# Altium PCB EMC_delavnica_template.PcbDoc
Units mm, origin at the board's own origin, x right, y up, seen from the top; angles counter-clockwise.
Board outline 117 x 59 mm, 2 copper layers (Top Layer, Bottom Layer), stack 1.536 mm thick; 45 components, 21 nets, 110 pads, 0 vias.
Unrouted connection lines stored in the file: 68.
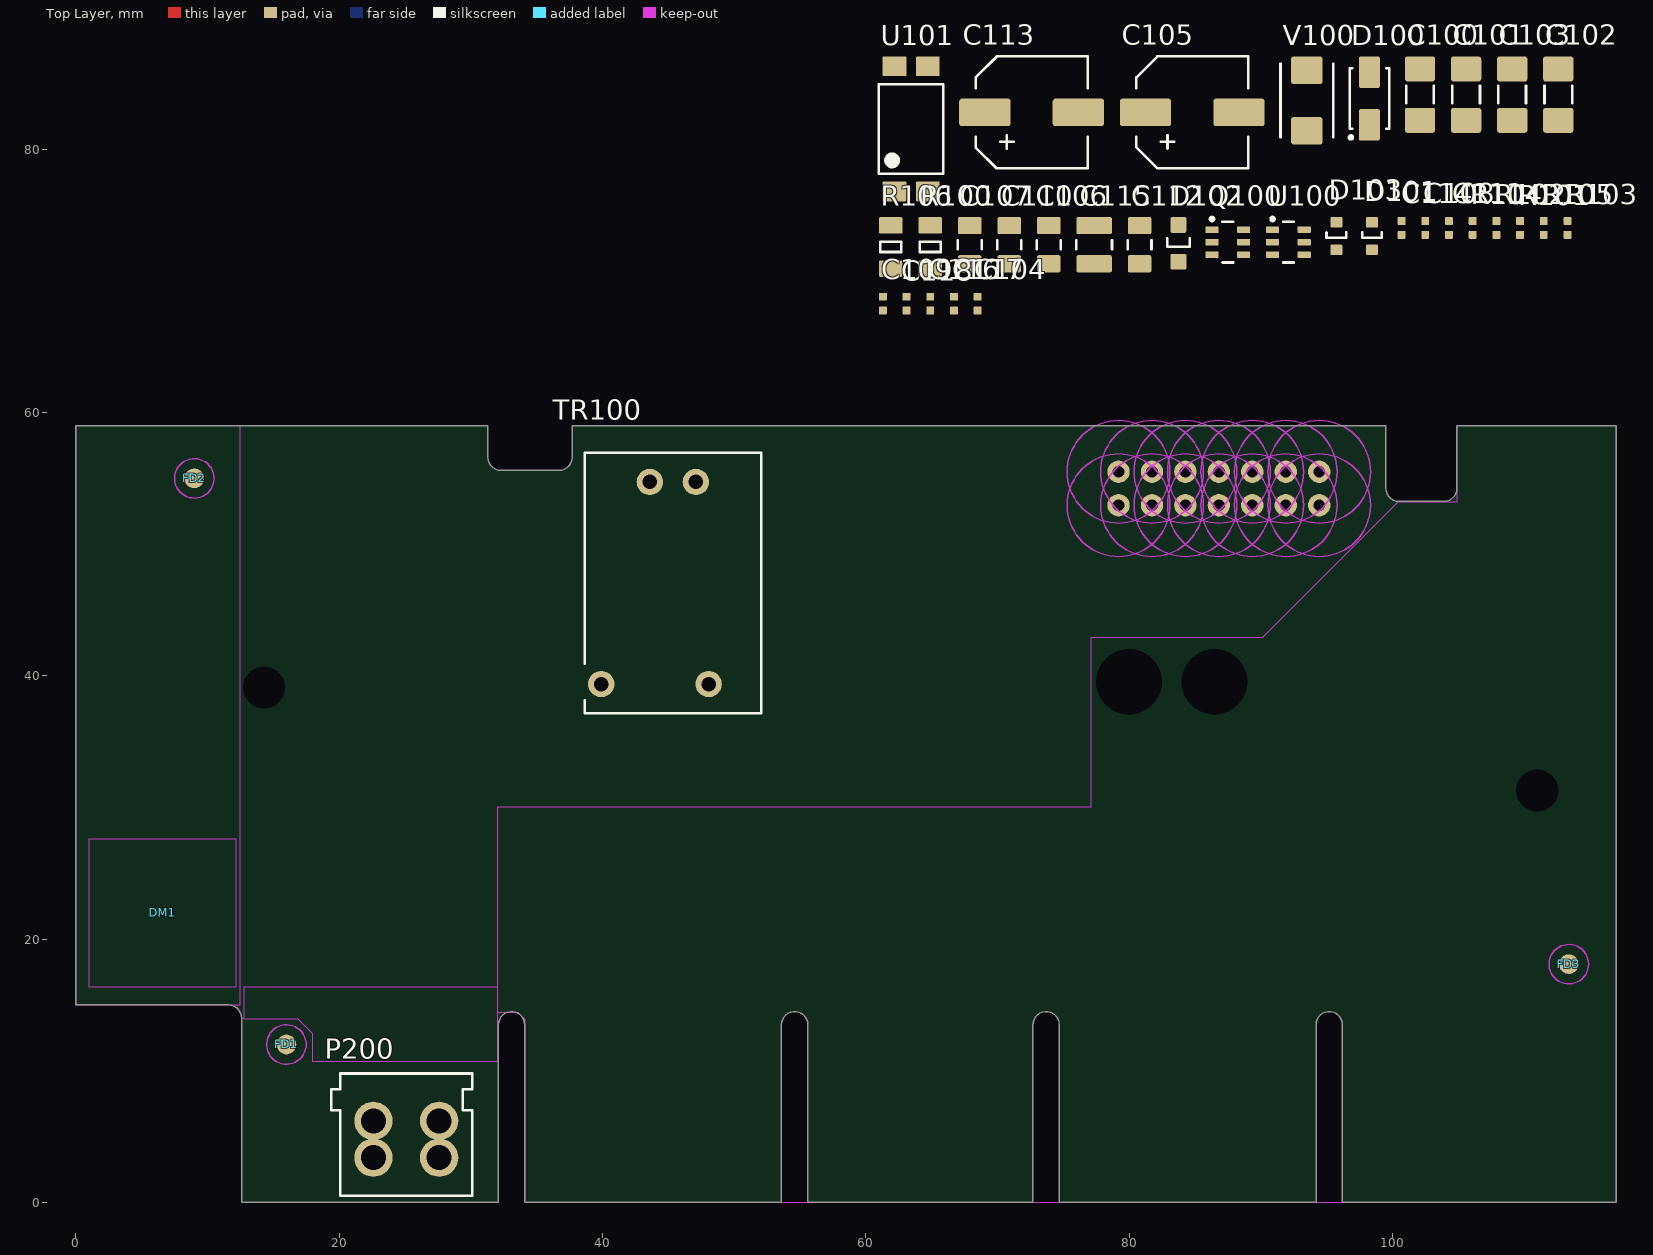
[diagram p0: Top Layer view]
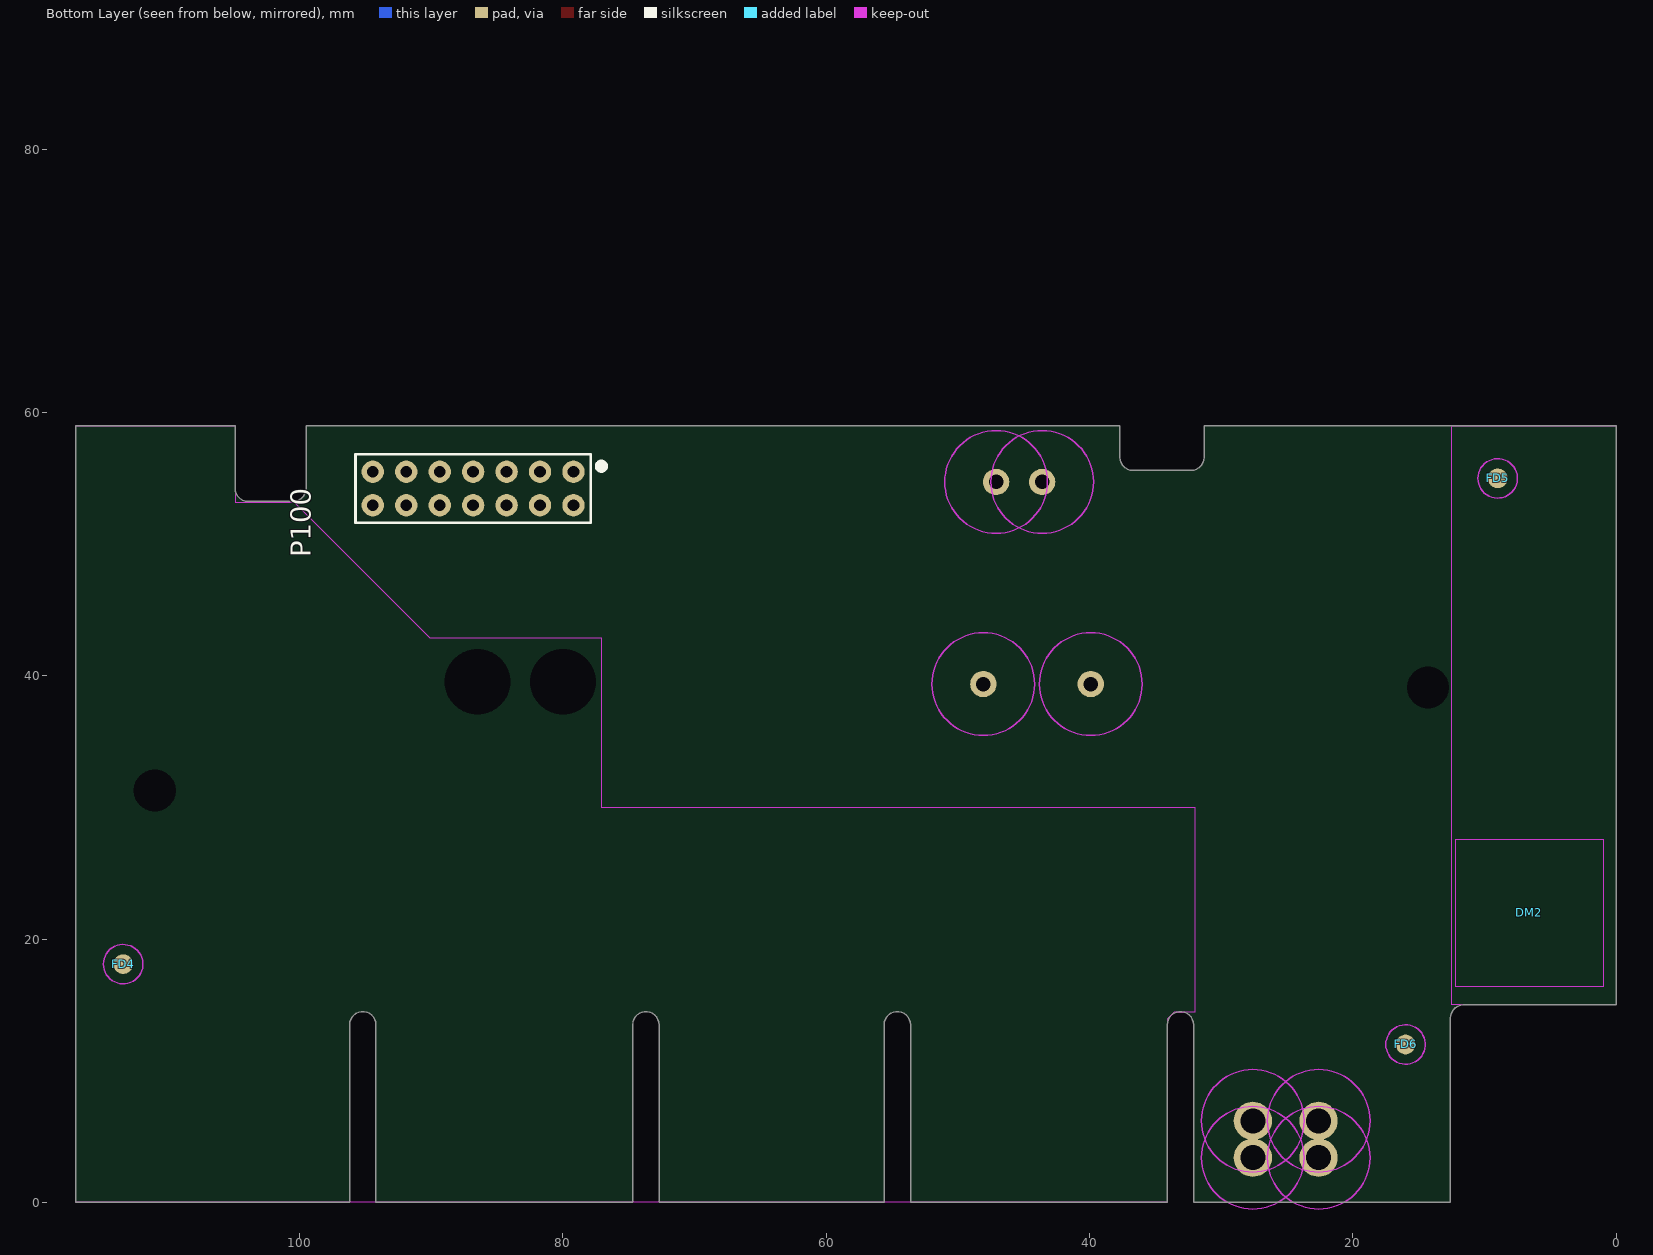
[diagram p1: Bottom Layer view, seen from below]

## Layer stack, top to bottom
Top Solder: solder mask 0.0102, Solder Resist, Dk 3.5
Top Layer: signal copper 0.018
Dielectric 3: core 1.5, FR-4, Dk 4.2
Bottom Layer: signal copper 0.018
Bottom Solder: solder mask 0.0102, Solder Resist, Dk 3.5

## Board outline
12.6,0 32.1,0 32.1,13.5 32.122,13.708 32.186,13.907 32.291,14.088 32.431,14.243 32.6,14.366 32.791,14.451 32.995,14.495 33.205,14.495 33.409,14.451 33.6,14.366 33.769,14.243 33.909,14.088 34.014,13.907 34.078,13.708 34.1,13.5 34.1,0 53.6,0 53.6,13.5 53.622,13.708 53.686,13.907 53.791,14.088 53.931,14.243 54.1,14.366 54.291,14.451 54.495,14.495 54.705,14.495 54.909,14.451 55.1,14.366 55.269,14.243 55.409,14.088 55.514,13.907 55.578,13.708 55.6,13.5 55.6,0 72.7,0 72.7,13.5 72.722,13.708 72.786,13.907 72.891,14.088 73.031,14.243 73.2,14.366 73.391,14.451 73.595,14.495 73.805,14.495 74.009,14.451 74.2,14.366 74.369,14.243 74.509,14.088 74.614,13.907 74.678,13.708 74.7,13.5 74.7,0 94.2,0 94.2,13.5 94.222,13.708 94.286,13.907 94.391,14.088 94.531,14.243 94.7,14.366 94.891,14.451 95.095,14.495 95.305,14.495 95.509,14.451 95.7,14.366 95.869,14.243 96.009,14.088 96.114,13.907 96.178,13.708 96.2,13.5 96.2,0 117,0 117,59 104.9,59 104.9,54.25 104.875,54.027 104.801,53.816 104.682,53.627 104.523,53.468 104.334,53.349 104.123,53.275 103.9,53.25 100.5,53.25 100.277,53.275 100.066,53.349 99.876,53.468 99.718,53.627 99.599,53.816 99.525,54.027 99.5,54.25 99.5,59 37.7,59 37.7,56.6 37.675,56.377 37.601,56.166 37.482,55.977 37.323,55.818 37.134,55.699 36.923,55.625 36.7,55.6 32.3,55.6 32.077,55.625 31.866,55.699 31.677,55.818 31.518,55.977 31.399,56.166 31.325,56.377 31.3,56.6 31.3,59 0,59 0,15 11.6,15 11.823,14.975 12.034,14.901 12.223,14.782 12.382,14.623 12.501,14.434 12.575,14.223 12.6,14

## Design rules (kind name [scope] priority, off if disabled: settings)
BoardOutlineClearance BoardOutlineClearance_placed_on_edge [HasFootprint('TIV-DATAMATRIX_11X11') OR HasFootprint('TIV-DATAMATRIX_8X11') OR InComponent('P200')] p1: gap=0 ignorepadtopadclearanceinfootprint=FALSE except(0.45: SMDPad-OutlineEdge SMDPad-CavityEdge SMDPad-CutoutEdge SMDPad-SplitBarrior THPad-OutlineEdge THPad-CavityEdge THPad-CutoutEdge THPad-SplitBarrior Fill-OutlineEdge Fill-CavityEdge Fill-CutoutEdge Fill-SplitBarrior Poly-OutlineEdge Poly-CavityEdge Poly-CutoutEdge Poly-SplitBarrior Region-OutlineEdge Region-CavityEdge Region-CutoutEdge Region-SplitBarrior; 0.5: Via-OutlineEdge Via-CavityEdge Via-CutoutEdge Via-SplitBarrior)
BoardOutlineClearance [All] p2: gap=0.45 ignorepadtopadclearanceinfootprint=FALSE except(0: Arc-OutlineEdge Arc-CavityEdge Arc-CutoutEdge Arc-SplitBarrior Arc-SplitContinuation Track-SplitContinuation SMDPad-SplitContinuation THPad-SplitContinuation Via-SplitContinuation Fill-SplitContinuation Poly-SplitContinuation Region-SplitContinuation Text-OutlineEdge Text-CavityEdge Text-CutoutEdge Text-SplitBarrior Text-SplitContinuation; 0.5: Via-OutlineEdge Via-CavityEdge Via-CutoutEdge Via-SplitBarrior)
Clearance Clearance_keepout_vs_freePad [(IsFree and IsPad) or HasFootprint('TIV-FID15X30') vs OnLayer('Keep-Out Layer')] p1: gap=0.15 ignorepadtopadclearanceinfootprint=TRUE except(0: Arc-Arc Arc-Track Arc-SMDPad Arc-THPad Arc-Hole Track-Hole SMDPad-Fill SMDPad-Poly SMDPad-Region SMDPad-Hole THPad-Fill THPad-Poly THPad-Region THPad-Hole Via-Hole Fill-Hole Poly-Hole Region-Hole Text-Hole; 0.2: Track-Track Track-SMDPad Track-THPad SMDPad-Via SMDPad-Text THPad-Via THPad-Text Via-Via; 0.5: SMDPad-SMDPad SMDPad-THPad THPad-THPad)
Clearance [All] p2: gap=0.15 ignorepadtopadclearanceinfootprint=TRUE except(0: Arc-Arc Arc-Track Arc-SMDPad Arc-THPad Arc-Hole Track-Hole SMDPad-Hole THPad-Hole Via-Hole Fill-Hole Poly-Hole Region-Hole Text-Hole; 0.2: Track-Track Track-SMDPad Track-THPad SMDPad-Via SMDPad-Fill SMDPad-Poly SMDPad-Region SMDPad-Text THPad-Via THPad-Fill THPad-Poly THPad-Region THPad-Text Via-Via; 0.5: SMDPad-SMDPad SMDPad-THPad THPad-THPad)
ComponentClearance ComponentClearance_TIV [HasFootprint('TIV-FID15X30') OR HasFootprint('TIV-DATAMATRIX_8X11') OR HasFootprint('TIV-CODE') OR HasFootprint('TIV-FIRM') OR HasFootprint('TIV-DATE') OR HasFootprint('TIV-DATAMATRIX_11x11') OR HasFootprint('TIV-LAYER-NAME') OR HasFootprint('TIV-LAYER-NUM4') OR HasFootprint('TIV-LAYER-NUM6') OR HasFootprint('TIV-CODE-NUM4') OR HasFootprint('TIV-CODE-NUM6') OR HasFootprint('TIV-DATE-NUM4') OR HasFootprint('TIV-DATE-NUM6') OR HasFootprint('TIV-DESIGNER-NUM4') OR HasFootprint('TIV-DESIGNER-NUM6') OR HasFootprint('TIV-FIRM-NUM4') OR HasFootprint('TIV-FIRM-NUM6') OR HasFootprint('TIV-TARGET') OR HasFootprint('TIV-TARGET-NUM4') OR HasFootprint('TIV-TARGET-NUM6') OR HasFootprint('TIV-CODE')] p1: gap=0 collisioncheckmode=3 verticalgap=0 showdistances=FALSE
ComponentClearance [All] p2: gap=0.5 collisioncheckmode=3 verticalgap=0.5 showdistances=FALSE
Height Height_bottom [(OnLayer('Bottom Layer') and not InComponent('P100'))] p1: minheight=0 maxheight=3 prefheight=3
Height Height_top [(OnLayer('Top Layer'))] p2: minheight=0 maxheight=50 prefheight=25
HoleSize [All] p1: absolutevalues=TRUE maxlimit=6.4 minlimit=0.3 maxpercent=80.000 minpercent=20.000
MinimumSolderMaskSliver [InPadClass('All Pads') vs InPadClass('All Pads')] p1: minsoldermaskwidth=0.2
ParallelSegment [All] p1: limit=254 gap=0.254
PasteMaskExpansion [All] p1: expansion=-0.05
PermittedLayers [All] p1: toplayerpermitted=TRUE bottomlayerpermitted=TRUE
PlaneConnect [All] p1: pad.planeconnectstyle=Relief pad.reliefexpansion=0.5 pad.reliefentries=4 pad.reliefconductorwidth=0.2 pad.reliefairgap=0.2 via.planeconnectstyle=Direct via.reliefexpansion=0.5 via.reliefentries=4 via.reliefconductorwidth=0.2 via.reliefairgap=0.2
PolygonConnect [All] p1: thpad.connectstyle=Relief thpad.reliefconductorwidth=0.4 thpad.reliefentries=4 thpad.polygonreliefangle="90 Angle" thpad.airgapwidth=0.2 smdpad.connectstyle=Relief smdpad.reliefconductorwidth=0.4 smdpad.reliefentries=4 smdpad.polygonreliefangle="90 Angle" smdpad.airgapwidth=0.2 via.connectstyle=Direct via.reliefconductorwidth=0.254 via.reliefentries=4 via.polygonreliefangle="90 Angle" via.airgapwidth=0.254
RoutingVias [All] p1: holewidth=0.4 width=0.7 viastyle="Through Hole" minholewidth=0.4 minwidth=0.7 maxholewidth=0.5 maxwidth=1
SMDEntry [All] p1: side=TRUE corner=TRUE anyangle=TRUE
SMDToCorner [All] p1: distance=0
SilkToSilkClearance [All] p1: silktosilkclearance=0.2
SilkToSolderMaskClearance [IsPad] p1: minsilkscreentomaskgap=0.2 clearancetoexposedcopper=TRUE
SolderMaskExpansion [All] p1: expansion=0.1 istentingtop=FALSE
UnRoutedNet [All] p1: checkbadconnections=TRUE
Width [All] p1: maxlimit=2 minlimit=0.2 preferedwidth=0.2
21 further rules are at their usual default settings.

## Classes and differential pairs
component class Sheet1: C104 C105 C108 C111 C113 C114 C115 C116 C117 C118 D100 D101 D102 D103 DM1 DM2 FD1 FD2 FD3 FD4 FD5 FD6 P100 P200 Q100 R100 R101 R102 R103 R106 TR100 U100 U101 V100

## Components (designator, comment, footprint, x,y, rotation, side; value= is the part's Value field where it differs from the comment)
C100 "613070511000" CAPC4520 102.1,84.146 r90 top value=1n
C101 "613070511000" CAPC4520 105.6,84.146 r90 top value=1n
C102 "613070511000" CAPC4520 112.6,84.146 r90 top value=1n
C103 "613070511000" CAPC4520 109.1,84.146 r90 top value=1n
C104 "613070392000" CAPC1005 68.5,68.271 r90 top value=33p
C105 "614000031000" CAPAE83W105H 84.8,82.796 r0 top value=100u
C106 "613070488000" CAPC3216 73.9,72.746 r90 top value=4u7
C107 "613070488000" CAPC3216 67.9,72.746 r90 top value=4u7
C108 "613070438000" CAPC1005 102.5,74.021 r90 top value=100n
C109 "613070392000" CAPC1005 61.3,68.271 r90 top value=33p
C110 "613070323000" CAPC3216 70.9,72.746 r90 top value=1n
C111 "613070438000" CAPC1005 104.3,74.021 r90 top value=100n
C112 "613070488000" CAPC3216 80.8,72.746 r90 top value=4u7
C113 "614000032000" CAPAE83W105H 72.6,82.796 r0 top value=100u
C114 "613070346000" CAPC1005 100.7,74.021 r90 top value=220p
C115 "613070255000" CAPC3225 77.35,72.746 r90 top value=1u
C116 "613070438000" CAPC1005 64.9,68.271 r90 top value=100n
C117 "613070392000" CAPC1005 66.7,68.271 r90 top value=33p
C118 "613070393000" CAPC1005 63.1,68.271 r90 top value=100p
D100 "623007589000" DIOSMDO214AC 98.25,83.846 r90 top value="1000V 1A"
D101 "623005265000" DIOSOD323 98.45,73.396 r90 top value=36V
D102 "623007586000" TVSDO219AB 83.75,72.846 r90 top value=MBR0540
D103 "623007671000" DIOSOD323 95.75,73.396 r90 top value=1N4148
DM1 "TIV-DATAMATRIX_11X11" TIV-DATAMATRIX_11x11 6.6,22 r0 top locked
DM2 "TIV-DATAMATRIX_11X11" TIV-DATAMATRIX_11x11 6.6,22 r180 bottom locked
FD1 "TIV-FID15X30" TIV-FID15X30 16,12 r90 top locked
FD2 "TIV-FID15X30" TIV-FID15X30 9,55 r90 top locked
FD3 "TIV-FID15X30" TIV-FID15X30 113.4,18.1 r90 top locked
FD4 "TIV-FID15X30" TIV-FID15X30 113.4,18.1 r90 bottom locked
FD5 "TIV-FID15X30" TIV-FID15X30 9,55 r90 bottom locked
FD6 "TIV-FID15X30" TIV-FID15X30 16,12 r90 bottom locked
P100 "027901066000" CON_G08PTIV_14-2V 86.82,54.23 r0 bottom locked value=14-2V
P200 "631000042000" CON_AK104-DS_2-1V 25.1,4.8 r0 top locked value=2-1V
Q100 "623004147000" SOT23-6 87.5,72.946 r0 top value=IRF5802
R100 "610422823000" RESMELF3516 64.9,72.571 r90 top value=26k7
R101 "610426055000" RESC1005 109.7,74.021 r90 top value=150R
R102 "610426100000" RESC1005 107.9,74.021 r90 top value=1k
R103 "610427445000" RESC1005 113.3,74.021 r90 top value=68k1
R104 "610427132000" RESC1005 106.1,74.021 r90 top value=10k
R105 "610427100000" RESC1005 111.5,74.021 r90 top value=1k
R106 "610422969000" RESMELF3516 61.9,72.571 r90 top value=1R21
TR100 "662000266000" XFMR_E13X20-4_9P-ZA_V1 45.35,47.05 r0 top locked value="AM500 MbusS"
U100 "665150862000" SOT23-6 92.1,72.946 r0 top value=AP3103KTR/SG6858TZ
U101 "623010015000" OPTODIP4-SMD8 63.45,81.546 r90 top value=SFH618A-3
V100 "619000024000" TVSDO214AA-5.6X4 93.5,83.696 r90 top value=54V

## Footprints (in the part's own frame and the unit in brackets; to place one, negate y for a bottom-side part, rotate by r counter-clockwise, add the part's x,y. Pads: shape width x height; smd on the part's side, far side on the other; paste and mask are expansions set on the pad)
CAPAE83W105H [mm] "Aluminum Electrolytic Capacitor, Body 8.30x8.30x10.50mm, IPC Low Density"
  rrect20% 3.9x2.1 smd paste-0.05 mask+0.1: 1(3.55,0) 2(-3.55,0)
  silkscreen extent -4.25,-4.25 4.25,4.25, body extent -4.95,-4.25 4.95,4.25, height 10.5
CAPC1005 [mm] "Chip Capacitor, 2-Leads, Body 1.00x0.50mm, IPC Medium Density"
  rrect20% 0.6x0.6 smd paste-0.05 mask+0.1: 1(-0.525,0) 2(0.525,0)
  body extent -0.55,-0.3 0.55,0.3, height 0.6
CAPC3216 [mm] "Chip Capacitor, 2-Leads, Body 3.20x1.60mm, IPC Medium Density"
  rrect20% 1.3x1.8 smd paste-0.05: 1(-1.45,0) 2(1.45,0)
  silkscreen extent -0.35,-0.9 0.35,0.9, body extent -1.7,-0.9 1.7,0.9, height 1.35
CAPC3225 [mm] "Chip Capacitor 1210, 2-Leads, Body 3.20x2.50mm, IPC Medium Density"
  rrect20% 1.3x2.7 smd paste-0.05 mask+0.1: 1(-1.45,0) 2(1.45,0)
  silkscreen extent -0.35,-1.35 0.35,1.35, body extent -1.7,-1.35 1.7,1.35, height 2.3
CAPC4520 [mm] "Chip Capacitor, 2-Leads, Body 5,00x2,30mm, IPC Medium Density"
  rrect20% 1.9x2.3 smd paste-0.05 mask+0.1: 1(-1.95,0) 2(1.95,0)
  silkscreen extent -0.66,-1.05 0.66,1.05, body extent -2.5,-1.15 2.5,1.15, height 2.2
CON_AK104-DS_2-1V [mm] "Sponka vrstna 2/1, 5mm raster"
  round 2.9 hole 1.9: 1(-2.5,-1.4) 1(-2.5,1.4) 2(2.5,-1.4) 2(2.5,1.4)
  Bottom Layer keep-out circle w0.1: c2.5,1.4 r3.9
  Bottom Layer keep-out circle w0.1: c2.5,-1.4 r3.9
  Bottom Layer keep-out circle w0.1: c-2.5,1.4 r3.9
  Bottom Layer keep-out circle w0.1: c-2.5,-1.4 r3.9
  silkscreen extent -5.7,-4.3 5,5, body extent -5.7,-4.3 5,5, height 12.8
CON_G08PTIV_14-2V [mm] "DIP 14/2 2.54mm"
  round 1.7 hole 0.9: 1(-7.62,-1.27) 2(-7.62,1.27) 3(-5.08,-1.27) 4(-5.08,1.27) 5(-2.54,-1.27) 6(-2.54,1.27) 7(0,-1.27) 8(0,1.27) 9(2.54,-1.27) 10(2.54,1.27) 11(5.08,-1.27) 12(5.08,1.27) 13(7.62,-1.27) 14(7.62,1.27)
  Bottom Layer keep-out circle w0.1: c7.62,-1.27 r3.9
  Bottom Layer keep-out circle w0.1: c7.62,1.27 r3.9
  Bottom Layer keep-out circle w0.1: c5.08,1.27 r3.9
  Bottom Layer keep-out circle w0.1: c5.08,-1.27 r3.9
  Bottom Layer keep-out circle w0.1: c2.54,-1.27 r3.9
  Bottom Layer keep-out circle w0.1: c2.54,1.27 r3.9
  Bottom Layer keep-out circle w0.1: c0,-1.27 r3.9
  Bottom Layer keep-out circle w0.1: c0,1.27 r3.9
  Bottom Layer keep-out circle w0.1: c-2.54,-1.27 r3.9
  Bottom Layer keep-out circle w0.1: c-2.54,1.27 r3.9
  Bottom Layer keep-out circle w0.1: c-5.08,-1.27 r3.9
  Bottom Layer keep-out circle w0.1: c-5.08,1.27 r3.9
  Bottom Layer keep-out circle w0.1: c-7.62,-1.27 r3.9
  Bottom Layer keep-out circle w0.1: c-7.62,1.27 r3.9
  silkscreen extent -9.99,-2.6 8.94,2.6, body extent -8.89,-2.54 8.89,2.54, height 8.38
DIOSMDO214AC [mm] "Molded Diode, 2-Leads, Body 4.30x2.65mm, IPC Medium Density"
  rrect20% 2.4x1.6 smd paste-0.05 mask+0.1: 1(-2,0) 2(2,0)
  silkscreen extent -3.07,-1.5 2.3,1.52, body extent -2.52,-1.5 2.52,1.5, height 2.45
DIOSOD323 [mm] "SODFL, 2-Leads, Body 1.30x2.68mm, IPC Medium Density"
  rrect20% 0.8x0.9 smd paste-0.05 mask+0.1: 1(-1.05,0) 2(1.05,0)
  silkscreen extent -0.12,-0.75 0.28,0.75, body extent -1.34,-0.75 1.34,0.75, height 1.15
OPTODIP4-SMD8 [mm] "DIP4 SMD, 623010066, SFH618A optocoupler"
  rrect10% 1.5x1.8 smd paste-0.05 mask+0.1: 1(-4.75,1.27) 2(-4.75,-1.27) 3(4.75,-1.27) 4(4.75,1.27)
  silkscreen extent -3.4,-2.45 3.4,2.45, body extent -5.18,-2.45 5.18,2.45, height 4.1
RESC1005 [mm] "Chip Resistor, 2-Leads, Body 1.00x0.50mm, IPC Medium Density"
  rrect20% 0.6x0.6 smd paste-0.05 mask+0.1: 1(-0.525,0) 2(0.525,0)
  body extent -0.55,-0.3 0.55,0.3, height 0.4
RESMELF3516 [mm] "MELF Resistor, 2-Leads, Body 3.50x1.40mm, IPC Medium Density"
  rrect20% 1.25x1.8 smd paste-0.05 mask+0.1: 1(-1.65,0) 2(1.65,0)
  silkscreen extent -0.38,-0.8 0.41,0.8, body extent -1.75,-0.7 1.75,0.7, height 1.4
SOT23-6 [mm] "SOT23, 6-Leads, Body 2.90x1.60mm, Pitch 0.95mm, IPC Medium Density"
  rrect20% 1x0.5 smd paste-0.05 mask+0.1: 1(-1.2,0.95) 2(-1.2,0) 3(-1.2,-0.95) 4(1.2,-0.95) 5(1.2,0) 6(1.2,0.95)
  silkscreen extent -1.32,-1.55 0.41,1.87, body extent -1.3,-1.5 1.3,1.5, height 1.1
TIV-DATAMATRIX_11x11 [mm] "DATAMATRIX_11x11"
  Top Layer keep-out region: -5.6,-5.6 5.6,-5.6 5.6,5.6 -5.6,5.6
TIV-FID15X30 [mm] "Fiducial 1.5mm cooper 3mm resist"
  round 1.5 smd paste-0.75 mask+0.75: ""(0,0)
  Top Layer pour cut-out: 0,-1.7 -0.651,-1.571 -1.202,-1.202 -1.571,-0.651 -1.7,0 -1.7,0 -1.571,0.651 -1.202,1.202 -0.651,1.571 0,1.7 0,1.7 0.651,1.571 1.202,1.202 1.571,0.651 1.7,0 1.7,0 1.571,-0.651 1.202,-1.202 0.651,-1.571 0,-1.7
  Top Layer keep-out circle w0.1: c0,0 r1.5
  body extent -0.75,-0.75 0.75,0.75
TVSDO214AA-5.6X4 [mm] "Molded Diode, 2-Leads, Body 5.35x3.63mm, IPC Medium Density"
  rrect20% 2.1x2.4 smd paste-0.05 mask+0.1: 1(-2.3,0) 2(2.3,0)
  silkscreen extent -2.8,-2 2.8,2, body extent -3.01,-1.97 3.03,1.97, height 2.65
TVSDO219AB [mm] "SODFL, 2-Leads, Body 1.55x3.70mm, IPC Medium Density"
  rrect20% 1.2x1.2 smd paste-0.05 mask+0.1: 1(-1.4,0) 2(1.4,0)
  silkscreen extent -0.25,-0.85 0.4,0.85, body extent -1.85,-0.85 1.85,0.85, height 1.35
XFMR_E13X20-4_9P-ZA_V1 [mm] "Transformer AM500 MbusS"
  round 2 hole 1.1: 1(-5.44,-7.675) 4(2.72,-7.675) 7(1.75,7.675) 8(-1.75,7.675)
  Bottom Layer keep-out circle w0.1: c1.75,7.675 r3.9
  Bottom Layer keep-out circle w0.1: c-1.75,7.675 r3.9
  Bottom Layer keep-out circle w0.1: c-5.44,-7.675 r3.9
  Bottom Layer keep-out circle w0.1: c2.72,-7.675 r3.9
  silkscreen extent -6.7,-9.9 6.7,9.9, body extent -6.7,-9.9 6.7,9.6, height 9.6

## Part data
C100 C101 C102 C103: library part 613070511000-4, "CAPACITOR", Package="SMD 1808 (4,5x2)", PART NAME="KOND X1/Y2 1808*1n 250V M", Tolerance=M-20%, Voltage=250V
C104 C109 C117: library part 613070392000-4, "CAPACITOR", Package="SMD 0402 (1x0,5)", PART NAME="KOND VP 0402 NP0*33p 50V J", Tolerance=J-5%, Voltage=50V
C105: library part 614000031000-7, "CAPACITOR polarized", Package="SMD 0810", PART NAME="KOND AL-SMD*100my 35V M", Tolerance=M-20%, Voltage=35V
C106 C107 C112: library part 613070488000-4, "CAPACITOR", Package="SMD 1206 (3,2x1,6)", PART NAME="KOND VP 1206 X7R*4,7my 50V K", Tolerance=K-10%, Voltage=50V
C108 C111 C116: library part 613070438000-4, "CAPACITOR", Package="SMD 0402 (1x0,5)", PART NAME="KOND VP 0402 X7R*100n 50V K", Tolerance=K-10%, Voltage=50V
C110: library part 613070323000-4, "CAPACITOR voltage type", Package="SMD 1206 (3,2x1,6)", PART NAME="KOND VP 1206 X7R*1n 2kV K", Tolerance=K-10%, Voltage=2kV
C113: library part 614000032000-7, "CAPACITOR polarized", Package="SMD 0810", PART NAME="KOND AL-SMD*100my 50V M", Tolerance=M-20%, Voltage=50V
C114: library part 613070346000-4, "CAPACITOR", Package="SMD 0402 (1x0,5)", PART NAME="KOND VP 0402 NP0*220p 50V J", Tolerance=J-5%, Voltage=50V
C115: library part 613070255000-4, "CAPACITOR", Package="SMD 1210 (3,2x2,5)", PART NAME="KOND VP 1210 X7R*1my 50V K", Tolerance=K-10%, Voltage=50V
C118: library part 613070393000-4, "CAPACITOR", Package="SMD 0402 (1x0,5)", PART NAME="KOND VP 0402 NP0*100p 50V J", Tolerance=J-5%, Voltage=50V
D100: library part 623007589000-5, "DIODE", Package="SMD DO214AC/SMA (4,3x2,7)", PART NAME="DIODA-U FUF1*1000V 1A", Voltage=1000V
D101: library part 623005265000-5, "DIODE Zener", Package="SMD SOD323 (1,7x1,3)", PART NAME="DIODA-Z BZX*36V J", Tolerance=J-5%, Voltage=36V
D102: library part 623007586000-5, "DIODE", Package="SMD SOD123 (3,1x1,9)", PART NAME="DIODA-SCH MBR0540*40V 0,5A", Voltage=40V
D103: library part 623007671000-6, "DIODE", Package="SMD SOD323 (1,7x1,3)", PART NAME="DIODA-ST 1N4148*75V 150mA", Voltage=75V
DM1 DM2: library part TIV-DATAMATRIX_11X11-4, "Datamatrix", PART NAME=DATAMATRIX_11x11
FD1 FD2 FD3 FD4 FD5 FD6: library part TIV-FID15X30-5, "Fiducial", PART NAME=FID15X30
P100: library part 027901066000-5, "Connector 14-2m", Package="THT RM{}2,54 mm", PART NAME="VTIC G08 5,8*14-2 V"
P200: library part 631000042000-5, "Connector 2-1f", Package="THT RM{}5,0 mm", PART NAME="SPONKA AK104-DS*2-1 V"
Q100: library part 623004147000-6, "MOSFET N Channel", Package="SMD SOT23-6/SOT26 (2,9x1,6) alias SSOT-6", PART NAME="TRANZISTOR MF-N*IRF5802"
R100: library part 610422823000-4, "RESISTOR TOL", Package="SMD SOD80/MiniMELF (3,6x1,4)", PART NAME="UPOR MPL SOD80*26,7K F 50", Tolerance=F-1%, Voltage=200V
R101: library part 610426055000-3, "RESISTOR", Package=1005(0402), PART NAME="UPOR DPL 0402*150R J 250", Tolerance=J-5%, Voltage=25V
R102: library part 610426100000-3, "RESISTOR", Package=1005(0402), PART NAME="UPOR DPL 0402*1K J 250", Tolerance=J-5%, Voltage=25V
R103: library part 610427445000-3, "RESISTOR TOL", Package=1005(0402), PART NAME="UPOR DPL 0402*68,1K F 100", Tolerance=F-1%, Voltage=25V
R104: library part 610427132000-3, "RESISTOR TOL", Package=1005(0402), PART NAME="UPOR DPL 0402*10K F 100", Tolerance=F-1%, Voltage=25V
R105: library part 610427100000-3, "RESISTOR TOL", Package=1005(0402), PART NAME="UPOR DPL 0402*1K F 100", Tolerance=F-1%, Voltage=25V
R106: library part 610422969000-5, "RESISTOR TOL", Package="SMD SOD80/MiniMELF (3,6x1,4)", PART NAME="UPOR MPL 0204*1,21R F 50", Tolerance=F-1%, Voltage=200V
TR100: library part 662000266000-6, "TRAFO STIK*AM500 MbusS", Package="THT E13/4, podaljšan tuljavnik (S) EF12,5"
U100: library part 665150862000-6, "VEZJE NADZ PWM - AP3103", Package="SMD SOT23-6/SOT26 (2,9x1,6) alias SSOT-6", PART NAME="VEZJE NADZ PWM 6858*I"
U101: library part 623010015000-5, "OPTOSKLOPNIK 4PIN", Package="SMD DIP4 P", PART NAME="OPTOSKLOPNIK SFH618A-3"
V100: library part 619000024000-5, "Transzorb 2way", Package="SMD DO214AA/SMB (4,4x3,6)", PART NAME="TRANSZORB 2-S*SMBJ 54V A", Voltage=54V

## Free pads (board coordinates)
  round 1.524 hole 3.2 unplated mask+0.1: ""(14.3,39.1)
  round 0 hole 5 unplated mask+0.1: ""(80,39.55) ""(86.5,39.55)
  round 0 hole 3.2 unplated mask+0.1: ""(111,31.3)

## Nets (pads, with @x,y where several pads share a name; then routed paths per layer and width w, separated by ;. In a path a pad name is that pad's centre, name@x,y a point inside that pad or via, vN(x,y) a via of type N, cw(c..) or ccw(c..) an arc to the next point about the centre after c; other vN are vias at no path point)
+3V3: P100.7
+UNREG: C105.2 C106.2 C107.2 C108.2 C109.2 C110.2 C115.2 C116.2 P100.3 R100.2 TR100.7 U100.5 V100.2
GND: C100.1 C105.1 C106.1 C107.1 C108.1 C109.1 C114.1 C115.1 C116.1 C118.1 P100.1 P100.5 P100.9 R103.1 R106.1 U100.1 U101.3
GND_ISO: C103.2 C111.1 C112.1 C113.1 C117.1 D103.2 R104.1 TR100.4 U101.2
MBUS_RX: P100.11
MBUS_TX: P100.8
NetC100_2: C100.2 C101.1
NetC101_2: C101.2 C102.1
NetC102_2: C102.2 C103.1
NetC104_1: C104.1 D100.2 TR100.1
NetC110_1: C110.1 D102.1 R100.1
NetC114_2: C114.2 Q100.3 R101.1
NetC117_2: C117.2 D103.1 R102.1 R104.2 U101.1
NetC118_2: C118.2 R105.2 U100.4
NetD101_2: D101.2 R102.2
NetD102_2: D102.2 Q100.1 Q100.2 Q100.5 Q100.6 TR100.8 V100.1
NetQ100_4: Q100.4 R105.1 R106.2
NetR101_2: R101.2 U100.6
NetR103_2: R103.2 U100.3
NetU100_2: U100.2 U101.4
UMBUS: C104.2 C111.2 C112.2 C113.2 D100.1 D101.1
pads on no net: FD1. FD2. FD3. FD4. FD5. FD6. P100.2 P100.4 P100.6 P100.10 P100.12 P100.13 P100.14 P200.1 P200.2

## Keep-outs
Top Layer:
  region: 12.8,16.4 32,16.4 32,10.7 18,10.7 18,12.8 16.893,13.907 12.8,13.907
Keep-Out Layer:
  rectangle: 0,15 12.5,59
  region: 32,30 32,14.44 33.56,14.44 34.1,13.9 34.1,0 117,0 117,59 104.9,59 104.9,53.2 100.4,53.2 90.1,42.9 77.1,42.9 77.1,30

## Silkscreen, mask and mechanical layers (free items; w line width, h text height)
Top Solder:
  the board outline again, w0.8
Bottom Solder:
  the board outline again, w0.8
Board Shape (Mech3):
  the board outline again, w0.1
